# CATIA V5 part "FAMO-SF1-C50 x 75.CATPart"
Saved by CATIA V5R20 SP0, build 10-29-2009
Part number: FAMO-SF1-C50 x 75
Definition: NONE
Nomenclature: FAMO-SF1-C50 x 75
Source: Unknown
Description: FAMO-SF1-C50 x 75
Bounding box of the stored display mesh (mm): x -40 to 35, y -39.5 to 39.5, z -39.5 to 39.5
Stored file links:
  C:\Users\Utente\Desktop\IO LAVORO\3D X SITO CF\X SITO\FAMO\FAMO-SF1-C50 x 75.CATPart

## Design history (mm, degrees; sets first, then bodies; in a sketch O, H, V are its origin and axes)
Body1 "FAMO-SF1-C50 x 75" (main body)
  Solid1: solid without history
